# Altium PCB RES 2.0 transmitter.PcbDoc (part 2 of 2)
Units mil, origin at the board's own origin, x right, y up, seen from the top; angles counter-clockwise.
Board outline 3335 x 2413 mil, 2 copper layers (Top Layer, Bottom Layer); 59 components, 51 nets, 223 pads, 116 vias.
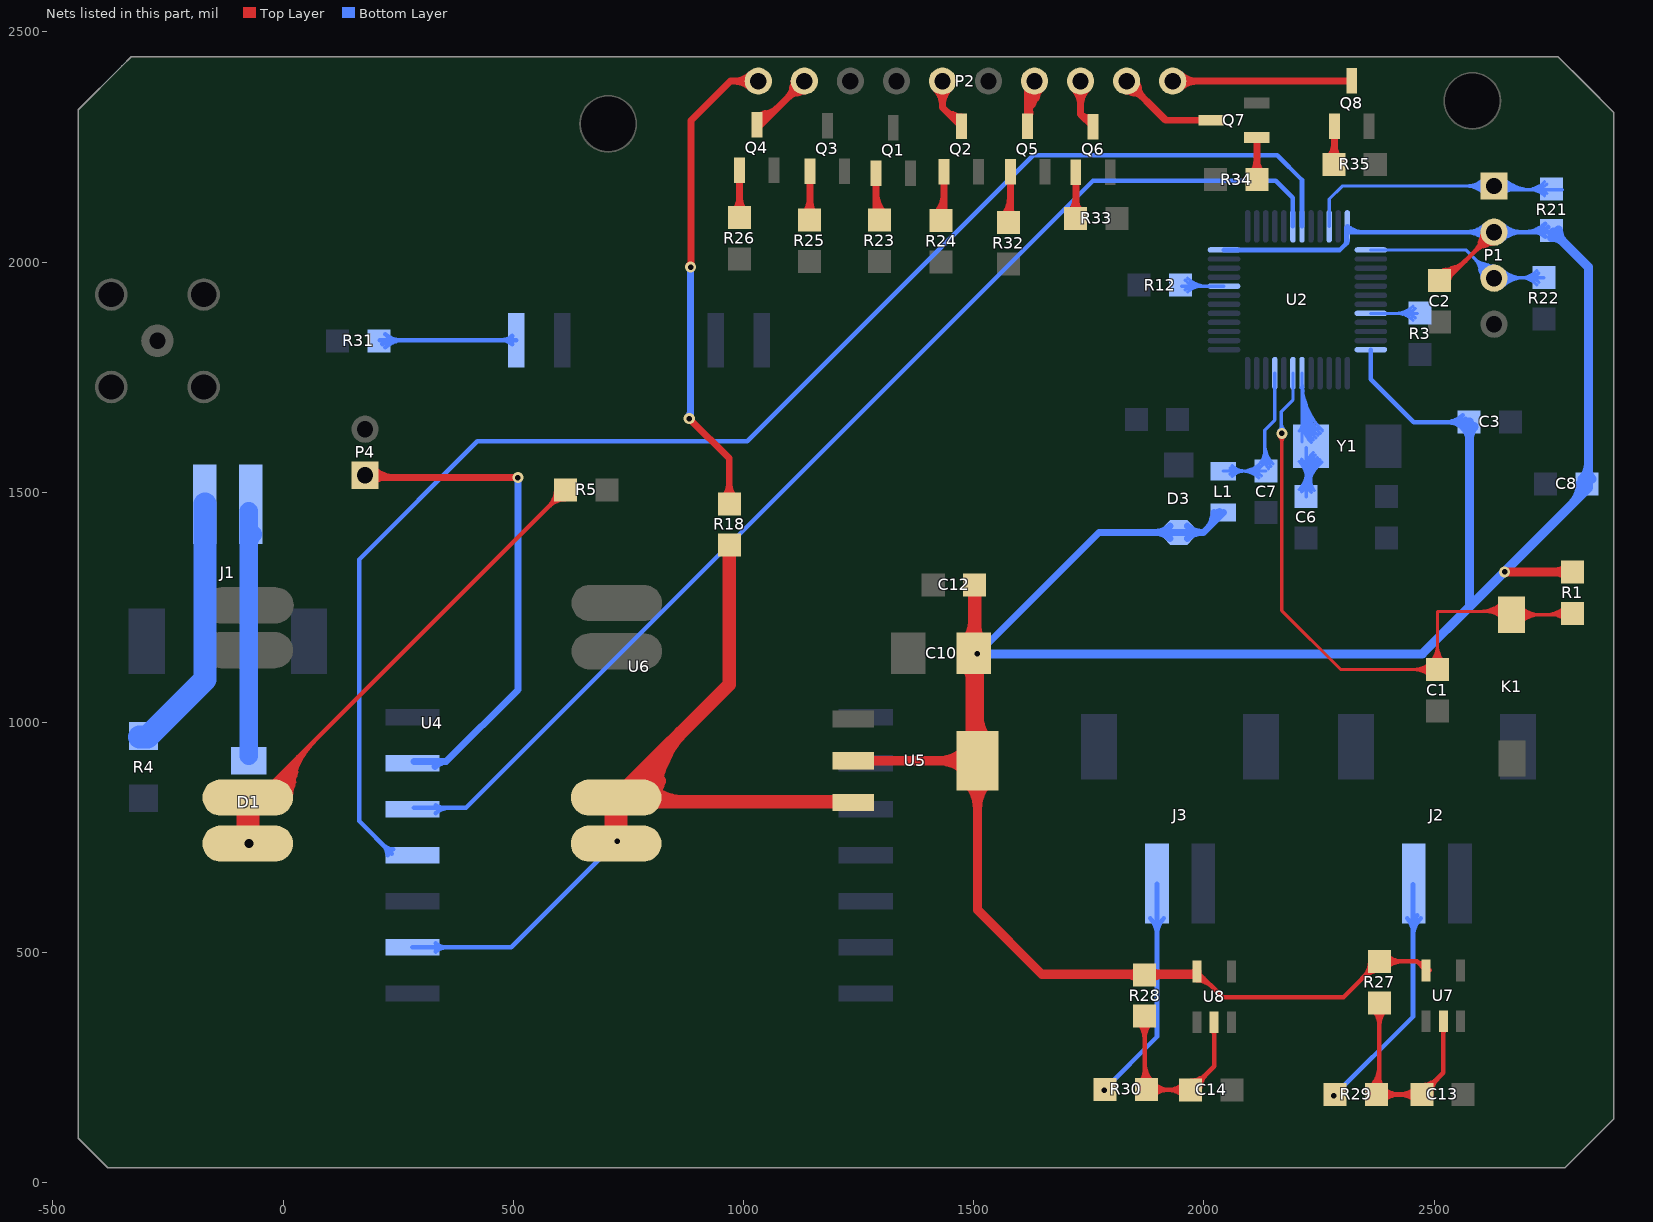
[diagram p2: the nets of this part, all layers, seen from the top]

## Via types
v1: diameter 24, hole 12, Top Layer to Bottom Layer, 115 vias
v2: diameter 40, hole 20, Top Layer to Bottom Layer, 1 vias

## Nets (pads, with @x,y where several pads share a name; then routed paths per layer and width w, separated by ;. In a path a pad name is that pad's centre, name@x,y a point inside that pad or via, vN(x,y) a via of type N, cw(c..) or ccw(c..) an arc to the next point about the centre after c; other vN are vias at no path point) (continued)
NetC6_2: C6.2 U2.6 Y1.1 | length 2958.8
  Bottom Layer w7: U2.6@2211.37,1727.12 cw(c2204.53,1718.24) 2215.65,1719.68 ; Y1.1@2212.84,1609.42 U2.6@2212.84,1758.55 ; 2213.02,1722.3 cw(c2220.09,1722.88) U2.6@2214.68,1727.47 ; 2217.94,1647.87 ccw(c2225.88,1652.46) Y1.1@2227.18,1643.38 ; 2220.47,1657.02 ccw(c2245.99,1671.75) Y1.1@2239.8,1642.94 ; C6.2@2222,1491 Y1.1@2222,1596.74 ; 2231.39,1648.9 ccw(c2242.91,1656.26) Y1.1@2239.97,1642.91 ; C6.2@2212,1510.03 ccw(c2199.11,1534.57) 2226.36,1529.54 ; C6.2@2212,1510.03 ccw(c2199.11,1534.57) 2226.36,1529.54 ; C6.2@2212,1510.03 ccw(c2199.11,1534.57) 2226.36,1529.54 ; C6.2@2212.42,1510.25 ccw(c2194.93,1545.37) 2233.07,1536.13 ; C6.2@2212.42,1510.25 ccw(c2194.93,1545.37) 2233.07,1536.13 ; C6.2@2212.42,1510.25 ccw(c2194.93,1545.37) 2233.07,1536.13 ; C6.2@2215.54,1503.98 ccw(c2203.7,1527.77) 2229.52,1521.51 ; C6.2@2215.54,1503.98 ccw(c2203.7,1527.77) 2229.52,1521.51 ; C6.2@2215.54,1503.98 ccw(c2203.7,1527.77) 2229.52,1521.51 ; 2222,1526.01 cw(c2186.99,1526.01) 2211.75,1501.25 ccw(c2186.99,1526.01) 2222,1526.01 ; 2222,1526.01 ccw(c2257.01,1526.01) 2232.25,1501.25 cw(c2257.01,1526.01) 2222,1526.01 ; 2222,1542.91 cw(c2170.09,1542.91) 2206.8,1506.2 ccw(c2170.09,1542.91) 2222,1542.91 ; 2222,1542.91 ccw(c2273.91,1542.91) 2237.2,1506.2 cw(c2273.91,1542.91) 2222,1542.91 ; 2224.33,1518.53 ccw(c2240.14,1515.62) C6.2@2230.6,1502.67 ; 2224.33,1518.53 ccw(c2240.14,1515.62) C6.2@2230.6,1502.67 ; 2224.33,1518.53 ccw(c2240.14,1515.62) C6.2@2230.6,1502.67 ; 2226.36,1529.54 ccw(c2247.52,1525.63) C6.2@2234.76,1508.31 ; 2226.36,1529.54 ccw(c2247.52,1525.63) C6.2@2234.76,1508.31 ; 2226.36,1529.54 ccw(c2247.52,1525.63) C6.2@2234.76,1508.31 ; 2229.48,1521.34 ccw(c2255.38,1515.06) C6.2@2233.76,1499.48 ; 2229.48,1521.34 ccw(c2255.38,1515.06) C6.2@2233.76,1499.48 ; 2229.48,1521.34 ccw(c2255.38,1515.06) C6.2@2233.76,1499.48 ; 2233.07,1536.13 ccw(c2271.63,1526.78) C6.2@2239.44,1503.57 ; 2233.07,1536.13 ccw(c2271.63,1526.78) C6.2@2239.44,1503.57 ; 2233.07,1536.13 ccw(c2271.63,1526.78) C6.2@2239.44,1503.57 ; Y1.1@2206.9,1566.76 cw(c2170.43,1530.3) 2222,1530.3 ccw(c2170.43,1530.3) Y1.1@2206.9,1566.76 ; Y1.1@2206.9,1633.24 ccw(c2192.54,1647.59) 2212.84,1647.59 cw(c2192.54,1647.59) Y1.1@2206.9,1633.24 ; Y1.1@2211.85,1571.71 cw(c2187.33,1547.2) 2222,1547.2 ccw(c2187.33,1547.2) Y1.1@2211.85,1571.71 ; 2212.84,1656.85 ccw(c2281.24,1656.85) 2232.88,1608.49 cw(c2281.24,1656.85) 2212.84,1656.85 ; 2212.84,1673.75 ccw(c2298.14,1673.75) 2237.82,1613.44 cw(c2298.14,1673.75) 2212.84,1673.75 ; 2212.84,1690.65 ccw(c2315.04,1690.65) 2242.77,1618.39 cw(c2315.04,1690.65) 2212.84,1690.65 ; 2212.84,1707.55 ccw(c2331.94,1707.55) 2247.72,1623.34 cw(c2331.94,1707.55) 2212.84,1707.55 ; U2.6@2212.84,1724.45 ccw(c2348.84,1724.45) 2252.67,1628.29 cw(c2348.84,1724.45) U2.6@2212.84,1724.45 ; U2.6@2212.84,1741.35 ccw(c2365.74,1741.35) 2257.62,1633.24 cw(c2365.74,1741.35) U2.6@2212.84,1741.35 ; C6.2@2222,1490.48 cw(c2321.17,1490.48) 2255.88,1565.13 ccw(c2321.17,1490.48) C6.2@2222,1490.48 ; C6.2@2222,1505.91 cw(c2307.68,1505.91) 2251.27,1570.4 ccw(c2307.68,1505.91) C6.2@2222,1505.91 ; 2222,1521.33 cw(c2294.19,1521.33) 2246.66,1575.67 ccw(c2294.19,1521.33) 2222,1521.33 ; 2222,1536.76 cw(c2280.7,1536.76) 2242.05,1580.93 ccw(c2280.7,1536.76) 2222,1536.76 ; 2222,1552.18 cw(c2267.2,1552.18) 2237.44,1586.2 ccw(c2267.2,1552.18) 2222,1552.18
NetC7_2: C7.2 L1.2 U2.9 | length 1085.4
  Bottom Layer w7: L1.2@2042,1546 C7.2@2135,1546 ; C7.2@2132,1563 2132,1635 2153.79,1656.79 U2.9@2153.79,1758.55 ; 2072.43,1546 cw(c2072.43,1568.93) 2056.22,1552.72 ccw(c2072.43,1568.93) 2072.43,1546 ; 2072.43,1546 ccw(c2072.43,1523.07) 2056.22,1539.28 cw(c2072.43,1523.07) 2072.43,1546 ; 2083.09,1546 cw(c2083.09,1494.09) 2119.8,1530.8 ccw(c2083.09,1494.09) 2083.09,1546 ; 2083.09,1546 ccw(c2083.09,1597.91) C7.2@2119.8,1561.2 ; 2083.09,1546 ccw(c2083.09,1597.91) C7.2@2119.8,1561.2 ; 2089.33,1546 cw(c2089.33,1585.83) 2061.17,1557.67 ccw(c2089.33,1585.83) 2089.33,1546 ; 2089.33,1546 ccw(c2089.33,1506.17) 2061.17,1534.33 cw(c2089.33,1506.17) 2089.33,1546 ; 2099.99,1546 cw(c2099.99,1510.99) 2124.75,1535.75 ccw(c2099.99,1510.99) 2099.99,1546 ; 2099.99,1546 ccw(c2099.99,1581.01) C7.2@2124.75,1556.25 ; 2099.99,1546 ccw(c2099.99,1581.01) C7.2@2124.75,1556.25 ; C7.2@2119.8,1561.2 ccw(c2090.34,1590.66) 2132,1590.66 cw(c2090.34,1590.66) C7.2@2119.8,1561.2 ; C7.2@2124.75,1556.25 ccw(c2107.24,1573.76) 2132,1573.76 cw(c2107.24,1573.76) C7.2@2124.75,1556.25 ; 2132,1571.35 ccw(c2160.35,1571.35) 2140.3,1551.3 cw(c2160.35,1571.35) 2132,1571.35 ; 2132,1588.25 ccw(c2177.25,1588.25) 2145.25,1556.25 cw(c2177.25,1588.25) 2132,1588.25 ; 2132,1605.15 ccw(c2194.15,1605.15) 2150.2,1561.2 cw(c2194.15,1605.15) 2132,1605.15
NetC13_2: C13.2 R27.2 R29.1 U7.2 | length 1400
  Top Layer w10: R29.1@2381,198 R27.2@2381,391 ; R29.1@2387,192 C13.2@2473,192 ; 2498.2,218.75 ccw(c2507.24,184.99) C13.2@2473,192 ; 2499.75,217.2 cw(c2465.99,226.24) C13.2@2473,192 ; U7.2@2520,350.89 2520,239 C13.2@2473,192 ; 2381,342.72 cw(c2429.28,342.72) 2395.14,376.86 ccw(c2429.28,342.72) 2381,342.72 ; 2381,342.72 ccw(c2332.72,342.72) 2366.86,376.86 cw(c2332.72,342.72) 2381,342.72 ; R29.1@2389.14,206.14 ccw(c2423.28,240.28) 2423.28,192 ; R29.1@2389.14,206.14 cw(c2408.8,225.8) 2381,225.8 ccw(c2408.8,225.8) R29.1@2389.14,206.14 ; R29.1@2389.14,206.14 ccw(c2423.28,240.28) 2423.28,192 ; 2423.28,192 ccw(c2423.28,143.72) 2389.14,177.86 cw(c2423.28,143.72) 2423.28,192 ; 2424.72,192 cw(c2424.72,143.72) 2458.86,177.86 ccw(c2424.72,143.72) 2424.72,192 ; 2424.72,192 ccw(c2424.72,240.28) 2458.86,206.14 cw(c2424.72,240.28) 2424.72,192 ; 2507.14,226.14 cw(c2473,260.28) 2473,212 ccw(c2473,260.28) 2507.14,226.14 ; 2507.14,226.14 ccw(c2541.28,192) 2493,192 cw(c2541.28,192) 2507.14,226.14 ; 2520,325.41 cw(c2531.69,325.41) 2523.43,333.68 ccw(c2531.69,325.41) 2520,325.41 ; 2520,325.41 ccw(c2508.31,325.41) 2516.58,333.68 cw(c2508.31,325.41) 2520,325.41 ; R29.1@2360.86,206.14 ccw(c2312.23,254.77) 2381,254.77 cw(c2312.23,254.77) R29.1@2360.86,206.14 ; R29.1@2367.93,199.07 ccw(c2336.37,230.63) 2381,230.63 cw(c2336.37,230.63) R29.1@2367.93,199.07
NetC14_2: C14.2 R28.2 R30.1 U8.2 | length 1393.2
  Top Layer w10: R30.1@1871,207 R28.2@1871,362 ; R30.1@1876,202 C14.2@1971,202 ; 1996.2,228.75 ccw(c2005.24,194.99) C14.2@1971,202 ; 1997.75,227.2 cw(c1963.99,236.24) C14.2@1971,202 ; U8.2@2022,348.89 2022,253 C14.2@1971,202 ; 1871,313.72 cw(c1919.28,313.72) 1885.14,347.86 ccw(c1919.28,313.72) 1871,313.72 ; 1871,313.72 ccw(c1822.72,313.72) 1856.86,347.86 cw(c1822.72,313.72) 1871,313.72 ; R30.1@1882.07,210.07 ccw(c1901.56,229.56) 1901.56,202 cw(c1901.56,229.56) R30.1@1882.07,210.07 ; R30.1@1882.07,210.07 cw(c1908.8,236.8) 1871,236.8 ccw(c1908.8,236.8) R30.1@1882.07,210.07 ; R30.1@1889.14,217.14 ccw(c1925.7,253.7) 1925.7,202 cw(c1925.7,253.7) R30.1@1889.14,217.14 ; R30.1@1889.14,217.14 cw(c1932.94,260.94) 1871,260.94 ccw(c1932.94,260.94) R30.1@1889.14,217.14 ; 1922.72,202 cw(c1922.72,153.72) 1956.86,187.86 ccw(c1922.72,153.72) 1922.72,202 ; 1922.72,202 ccw(c1922.72,250.28) 1956.86,216.14 cw(c1922.72,250.28) 1922.72,202 ; 2005.14,236.14 cw(c1971,270.28) 1971,222 ccw(c1971,270.28) 2005.14,236.14 ; 2005.14,236.14 ccw(c2039.28,202) 1991,202 cw(c2039.28,202) 2005.14,236.14 ; 2022,323.41 cw(c2033.69,323.41) 2025.43,331.68 ccw(c2033.69,323.41) 2022,323.41 ; 2022,323.41 ccw(c2010.31,323.41) 2018.58,331.68 cw(c2010.31,323.41) 2022,323.41 ; R30.1@1860.86,217.14 ccw(c1836.37,241.63) 1871,241.63 cw(c1836.37,241.63) R30.1@1860.86,217.14 ; R30.1@1889.14,188.86 cw(c1920.87,157.13) 1920.87,202 ccw(c1920.87,157.13) R30.1@1889.14,188.86
NetD1_1: D1.1 J1.2 | length 579
  Bottom Layer w40: D1.1@-75,928.03 J1.2@-75,1459 ; J1.2@-75,1387.41 cw(c-44.43,1387.41) -66.05,1409.02 ccw(c-44.43,1387.41) J1.2@-75,1387.41
NetJ1_1: J1.1 R4.1 | length 574.8
  Bottom Layer w50: R4.1@-312,968 -295,968 -170,1093 J1.1@-170,1474
NetJ2_2: J2.2 R29.2 | length 790.4
  Bottom Layer w10: v1(2282,189) 2454,361 J2.2@2454,648 ; 2293.95,200.95 cw(c2282,212.9) 2282,196 ccw(c2282,212.9) 2293.95,200.95 ; 2293.95,200.95 ccw(c2305.9,189) 2289,189 cw(c2305.9,189) 2293.95,200.95 ; J2.2@2441.44,574.42 cw(c2411.12,544.1) 2454,544.1 ccw(c2411.12,544.1) J2.2@2441.44,574.42 ; 2454,534.44 cw(c2510.54,534.44) 2470.56,574.42 ccw(c2510.54,534.44) 2454,534.44 ; 2454,558.58 cw(c2486.4,558.58) 2463.49,581.49 ccw(c2486.4,558.58) 2454,558.58
NetJ3_2: J3.2 R30.2 | length 704.9
  Bottom Layer w10: v1@1783,202 1898,317 J3.2@1898,650 ; 1898,539.27 cw(c1947.71,539.27) 1912.56,574.42 ccw(c1947.71,539.27) 1898,539.27 ; 1898,539.27 ccw(c1848.29,539.27) 1883.44,574.42 cw(c1848.29,539.27) 1898,539.27 ; v1@1783,208 ccw(c1783,222.49) 1793.24,212.24 cw(c1783,222.49) v1@1783,208 ; v1@1790,201 cw(c1809.31,201) 1795.66,214.66 ccw(c1809.31,201) v1@1790,201
  other v1: 1783,201
NetP2_1: P2.1 R18.1 | length 1401
  Top Layer w15: v1(882,1660) 969,1573 R18.1@969,1475 ; v1@886,1990 886,2307 972,2393 P2.1@1032,2393 ; 969,1517.25 cw(c926.75,1517.25) 956.63,1487.37 ccw(c926.75,1517.25) 969,1517.25 ; 969,1517.25 ccw(c1011.25,1517.25) 981.37,1487.37 cw(c1011.25,1517.25) 969,1517.25 ; 978.82,2393 cw(c978.82,2339.82) 1016.42,2377.42 ccw(c978.82,2339.82) 978.82,2393 ; 978.82,2393 ccw(c978.82,2446.18) 1016.42,2408.58 cw(c978.82,2446.18) 978.82,2393 ; v1@881.82,1992.18 ccw(c871.72,2002.28) 886,2002.28 cw(c871.72,2002.28) v1@881.82,1992.18
  Bottom Layer w15: v1@885,1663 v1(885,1989) ; v1@878.82,1663.18 ccw(c863.89,1678.11) 885,1678.11 cw(c863.89,1678.11) v1@878.82,1663.18
NetP4_1: P4.1 U6.2 | length 1307.5
  Top Layer w15: P4.1@178,1537 183,1532 v1(510,1532) ; P4.1@193.58,1521.42 cw(c219.11,1495.89) 219.11,1532 ccw(c219.11,1495.89) P4.1@193.58,1521.42 ; P4.1@193.58,1552.58 ccw(c243.25,1602.25) 243.25,1532 cw(c243.25,1602.25) P4.1@193.58,1552.58
  Bottom Layer w15: U6.2@284.18,915.19 354.19,915.19 ; v1(510,1532) 510,1071 354.19,915.19 ; 354.19,915.19 ccw(c354.19,881.58) 329.67,904.56 cw(c354.19,881.58) 354.19,915.19
NetQ1_1: Q1.1 R23.1 | length 276.5
  Top Layer w15: R23.1@1287.6,2098.4 Q1.1@1287.6,2193 ; R23.1@1282.63,2103.37 ccw(c1270.62,2115.38) 1287.6,2115.38 cw(c1270.62,2115.38) R23.1@1282.63,2103.37 ; R23.1@1287.6,2114.9 ccw(c1318.9,2114.9) 1296.77,2092.77 cw(c1318.9,2114.9) R23.1@1287.6,2114.9 ; 1287.6,2151.12 ccw(c1355.12,2151.12) 1307.37,2103.37 cw(c1355.12,2151.12) 1287.6,2151.12
NetQ2_1: Q2.1 R24.1 | length 232.1
  Top Layer w15: R24.1@1435.6,2096.6 Q2.1@1435.6,2196 ; R24.1@1416.63,2102.37 ccw(c1370.82,2148.18) 1435.6,2148.18 cw(c1370.82,2148.18) R24.1@1416.63,2102.37 ; 1435.6,2116.32 ccw(c1455.32,2116.32) 1441.37,2102.37 cw(c1455.32,2116.32) 1435.6,2116.32
NetQ3_1: Q3.1 R25.1 | length 237.1
  Top Layer w15: R25.1@1144.6,2092.6 Q3.1@1144.6,2197 ; R25.1@1130.63,2103.37 ccw(c1096.89,2137.11) 1144.6,2137.11 cw(c1096.89,2137.11) R25.1@1130.63,2103.37 ; 1144.6,2129.39 ccw(c1181.39,2129.39) 1155.37,2103.37 cw(c1181.39,2129.39) 1144.6,2129.39
NetQ4_1: Q4.1 R26.1 | length 234.1
  Top Layer w15: R26.1@991.6,2097.6 Q4.1@991.6,2199 ; R26.1@978.63,2109.37 ccw(c947.31,2140.69) 991.6,2140.69 cw(c947.31,2140.69) R26.1@978.63,2109.37 ; 991.6,2137.8 ccw(c1031.8,2137.8) 1003.37,2109.37 cw(c1031.8,2137.8) 991.6,2137.8
NetQ5_1: Q5.1 R32.1 | length 238.1
  Top Layer w15: R32.1@1579.6,2090.6 Q5.1@1579.6,2196 ; R32.1@1562.63,2098.37 ccw(c1521.65,2139.35) 1579.6,2139.35 cw(c1521.65,2139.35) R32.1@1562.63,2098.37 ; 1579.6,2117.15 ccw(c1606.15,2117.15) 1587.37,2098.37 cw(c1606.15,2117.15) 1579.6,2117.15
NetQ6_1: Q6.1 R33.1 | length 233
  Top Layer w15: Q6.1@1721,2194.4 Q6.1@1721.6,2195 R33.1@1721.6,2095.6 ; R33.1@1708.63,2107.37 ccw(c1677.31,2138.69) 1721.6,2138.69 cw(c1677.31,2138.69) R33.1@1708.63,2107.37 ; 1721.6,2135.8 ccw(c1761.8,2135.8) 1733.37,2107.37 cw(c1761.8,2135.8) 1721.6,2135.8
NetQ7_1: Q7.1 R34.1 | length 224.3
  Top Layer w15: R34.1@2115,2179 Q7.1@2115,2270.6 ; 2115,2221.25 cw(c2072.75,2221.25) 2102.63,2191.37 ccw(c2072.75,2221.25) 2115,2221.25 ; 2115,2221.25 ccw(c2157.25,2221.25) 2127.37,2191.37 cw(c2157.25,2221.25) 2115,2221.25
NetQ8_1: Q8.1 R35.1 | length 214.1
  Top Layer w15: R35.1@2283.6,2213.6 Q8.1@2283.6,2295 ; R35.1@2269.63,2224.37 ccw(c2235.89,2258.11) 2283.6,2258.11 cw(c2235.89,2258.11) R35.1@2269.63,2224.37 ; 2283.6,2250.39 ccw(c2320.39,2250.39) 2294.37,2224.37 cw(c2320.39,2250.39) 2283.6,2250.39
NetR3_1: R3.1 U2.44 | length 374.1
  Bottom Layer w7: U2.44@2362.45,1888.47 R3.1@2463.53,1888.47 ; 2415.82,1888.47 ccw(c2415.82,1942.18) 2453.8,1904.2 cw(c2415.82,1942.18) 2415.82,1888.47 ; 2418.37,1888.47 cw(c2418.37,1838.37) 2453.8,1873.8 ccw(c2418.37,1838.37) 2418.37,1888.47 ; 2432.72,1888.47 ccw(c2432.72,1925.28) 2458.75,1899.25 cw(c2432.72,1925.28) 2432.72,1888.47 ; 2435.27,1888.47 cw(c2435.27,1855.27) 2458.75,1878.75 ccw(c2435.27,1855.27) 2435.27,1888.47
NetR12_2: R12.2 U2.20 | length 365.1
  Bottom Layer w7: R12.2@1951.53,1947.53 U2.20@2043.55,1947.53 ; R12.2@1959.25,1939.75 cw(c1978.04,1920.96) 1978.04,1947.53 ccw(c1978.04,1920.96) R12.2@1959.25,1939.75 ; R12.2@1959.25,1960.25 ccw(c1989.97,1990.97) 1989.97,1947.53 cw(c1989.97,1990.97) R12.2@1959.25,1960.25 ; R12.2@1964.2,1934.8 cw(c1994.94,1904.06) 1994.94,1947.53 ccw(c1994.94,1904.06) R12.2@1964.2,1934.8 ; R12.2@1964.2,1965.2 ccw(c2006.87,2007.87) 2006.87,1947.53 cw(c2006.87,2007.87) R12.2@1964.2,1965.2
NetR31_2: R31.2 U6.18 | length 590.8
  Bottom Layer w10: R31.2@209.45,1830.45 U6.18@506.46,1830.45 ; 475.76,1830.45 cw(c475.76,1799.75) 497.47,1821.46 ccw(c475.76,1799.75) 475.76,1830.45 ; 475.76,1830.45 ccw(c475.76,1861.15) 497.47,1839.44 cw(c475.76,1861.15) 475.76,1830.45 ; R31.2@215.07,1821.93 cw(c235.64,1801.36) 235.64,1830.45 ccw(c235.64,1801.36) R31.2@215.07,1821.93 ; R31.2@222.14,1814.86 cw(c259.78,1777.22) 259.78,1830.45 ccw(c259.78,1777.22) R31.2@222.14,1814.86 ; R31.2@222.14,1843.14 ccw(c252.79,1873.79) 252.79,1830.45 cw(c252.79,1873.79) R31.2@222.14,1843.14
POWER1: P2.7 Q5.3 | length 497.1
  Top Layer w15: Q5.3@1614.85,2314.45 ccw(c1606.51,2328.9) 1622.62,2324.58 ; Q5.3@1617,2294.97 1617,2378 P2.7@1632,2393 ; P2.7@1618.42,2375.66 cw(c1611.34,2366.61) 1621.29,2360.87 cw(c1640.09,2350.01) P2.7@1636.08,2371.35 ; P2.7@1619.3,2375.01 cw(c1604.52,2354.08) 1626.7,2341.27 ; P2.7@1627.95,2387.26 cw(c1614.04,2367.56) 1634.92,2355.51 ; Q5.3@1617,2303.62 cw(c1721.38,2303.62) 1647.58,2377.42 ccw(c1721.38,2303.62) Q5.3@1617,2303.62 ; 1617,2339.83 cw(c1685.17,2339.83) 1636.97,2388.03 ccw(c1685.17,2339.83) 1617,2339.83
POWER2: P2.8 Q6.3 | length 352.9
  Top Layer w15: P2.8@1732,2393 1732,2320.98 ; 1738.58,2314.08 cw(c1738.35,2289.46) Q6.3@1755.93,2306.7 ; Q6.3@1759,2293.97 1732,2320.98 ; 1732,2320.98 ccw(c1751.17,2340.14) 1757.93,2313.9 cw(c1751.17,2340.14) 1732,2320.98 ; 1732,2339.82 cw(c1785.18,2339.82) 1747.58,2377.42 ccw(c1785.18,2339.82) 1732,2339.82 ; 1732,2339.82 ccw(c1678.82,2339.82) 1716.42,2377.42 cw(c1678.82,2339.82) 1732,2339.82
POWER3: P2.9 Q7.3 | length 457.3
  Top Layer w15: P2.9@1824.19,2391.4 ccw(c1855.58,2397.83) 1847.29,2366.88 ; P2.9@1832,2393 1917,2308 Q7.3@2016.03,2308 ; P2.9@1833.6,2400.81 cw(c1827.17,2369.42) 1858.12,2377.71 ; 1869.6,2355.4 cw(c1907.21,2393) 1854.03,2393 ccw(c1907.21,2393) 1869.6,2355.4 ; 1869.6,2355.4 ccw(c1832,2317.79) 1832,2370.97 cw(c1832,2317.79) 1869.6,2355.4
POWER4: P2.10 Q8.3 | length 576.7
  Top Layer w15: P2.10@1932,2393 Q8.3@2320.03,2393 ; 1985.18,2393 cw(c1985.18,2446.18) 1947.58,2408.58 ccw(c1985.18,2446.18) 1985.18,2393 ; 1985.18,2393 ccw(c1985.18,2339.82) 1947.58,2377.42 cw(c1985.18,2339.82) 1985.18,2393 ; 2308.25,2393 ccw(c2308.25,2406.73) 2317.96,2397.02 cw(c2308.25,2406.73) 2308.25,2393
RED: P2.2 Q4.3 | length 547.4
  Top Layer w15: Q4.3@1032.74,2311.57 cw(c1054.06,2299.25) 1047.69,2323.04 ; Q4.3@1036.97,2297.97 P2.2@1132,2393 ; 1105.88,2377.71 cw(c1136.83,2369.42) P2.2@1130.4,2400.81 ; 1116.71,2366.88 ccw(c1108.42,2397.83) P2.2@1139.81,2391.4 ; 1094.4,2355.4 cw(c1132,2317.79) 1132,2370.97 ccw(c1132,2317.79) 1094.4,2355.4 ; 1094.4,2355.4 ccw(c1056.79,2393) 1109.97,2393 cw(c1056.79,2393) 1094.4,2355.4 ; Q4.3@1029,2303.03 ccw(c1029,2334.48) 1051.24,2312.24 cw(c1029,2334.48) Q4.3@1029,2303.03 ; Q4.3@1029,2318.03 ccw(c1029,2385.69) 1076.85,2337.85 cw(c1029,2385.69) Q4.3@1029,2318.03
RESET: C1.2 K1.2 R1.1 U2.7 | length 3062.5
  Top Layer w7: v1(2169,1628) 2169,1243 2297,1115 C1.2@2507,1115 2507,1241 K1.2@2661,1241 ; K1.2@2668,1234 R1.1@2797,1234 ; 2169,1607.48 cw(c2189.52,1607.48) 2175.01,1621.99 ccw(c2189.52,1607.48) 2169,1607.48 ; 2169,1607.48 ccw(c2148.48,1607.48) 2162.99,1621.99 cw(c2148.48,1607.48) 2169,1607.48 ; 2455.09,1115 cw(c2455.09,1063.09) 2491.8,1099.8 ccw(c2455.09,1063.09) 2455.09,1115 ; 2455.09,1115 ccw(c2455.09,1166.91) C1.2@2491.8,1130.2 ; 2455.09,1115 ccw(c2455.09,1166.91) C1.2@2491.8,1130.2 ; 2471.99,1115 cw(c2471.99,1079.99) 2496.75,1104.75 ccw(c2471.99,1079.99) 2471.99,1115 ; 2471.99,1115 ccw(c2471.99,1150.01) C1.2@2496.75,1125.25 ; 2471.99,1115 ccw(c2471.99,1150.01) C1.2@2496.75,1125.25 ; C1.2@2491.8,1130.2 ccw(c2455.09,1166.91) 2507,1166.91 ; C1.2@2491.8,1130.2 ccw(c2455.09,1166.91) 2507,1166.91 ; C1.2@2496.75,1125.25 ccw(c2471.99,1150.01) 2507,1150.01 ; C1.2@2496.75,1125.25 ccw(c2471.99,1150.01) 2507,1150.01 ; 2507,1150.01 ccw(c2542.01,1150.01) 2517.25,1125.25 cw(c2542.01,1150.01) 2507,1150.01 ; 2507,1166.91 ccw(c2558.91,1166.91) 2522.2,1130.2 cw(c2558.91,1166.91) 2507,1166.91 ; 2713.94,1234 cw(c2713.94,1279.94) 2681.45,1247.45 ccw(c2713.94,1279.94) 2713.94,1234 ; 2713.94,1234 ccw(c2713.94,1188.06) 2681.45,1220.55 cw(c2713.94,1188.06) 2713.94,1234 ; 2730.84,1234 cw(c2730.84,1296.84) 2686.4,1252.4 ccw(c2730.84,1296.84) 2730.84,1234 ; 2730.84,1234 ccw(c2730.84,1171.16) 2686.4,1215.6 cw(c2730.84,1171.16) 2730.84,1234 ; 2598.3,1241 ccw(c2598.3,1313.54) 2649.6,1262.25 cw(c2598.3,1313.54) 2598.3,1241 ; 2612.03,1241 cw(c2612.03,1187.87) 2649.6,1225.44 ccw(c2612.03,1187.87) 2612.03,1241 ; 2615.2,1241 ccw(c2615.2,1296.64) 2654.55,1257.3 cw(c2615.2,1296.64) 2615.2,1241 ; 2628.93,1241 cw(c2628.93,1204.77) 2654.55,1230.39 ccw(c2628.93,1204.77) 2628.93,1241 ; 2632.1,1241 ccw(c2632.1,1279.74) 2659.5,1252.35 cw(c2632.1,1279.74) 2632.1,1241 ; 2740.85,1234 ccw(c2740.85,1296.15) 2784.8,1252.2 cw(c2740.85,1296.15) 2740.85,1234 ; 2755.34,1234 cw(c2755.34,1192.34) 2784.8,1221.8 ccw(c2755.34,1192.34) 2755.34,1234 ; 2757.75,1234 ccw(c2757.75,1279.25) 2789.75,1247.25 cw(c2757.75,1279.25) 2757.75,1234 ; 2772.24,1234 cw(c2772.24,1209.24) 2789.75,1226.75 ccw(c2772.24,1209.24) 2772.24,1234 ; 2774.65,1234 ccw(c2774.65,1262.35) 2794.7,1242.3 cw(c2774.65,1262.35) 2774.65,1234
  Bottom Layer w7: v1@2164,1630 2167.79,1633.79 2167.79,1674.79 2193.16,1700.16 U2.7@2193.16,1758.55 ; v1@2162.99,1634.01 ccw(c2151.41,1645.59) 2167.79,1645.59 cw(c2151.41,1645.59) v1@2162.99,1634.01 ; 2167.79,1651.45 ccw(c2192.45,1651.45) 2175.01,1634.01 cw(c2192.45,1651.45) 2167.79,1651.45
SWCLK: P1.3 R22.1 U2.37 | length 1589.2
  Bottom Layer w7: U2.37@2362.45,2026.27 2568.73,2026.27 P1.3@2630,1965 ; 2596.01,1994.71 ccw(c2638.41,2006.07) P1.3@2629.6,1963.07 ; 2598.94,1983.77 ccw(c2635.87,1993.66) P1.3@2628.2,1956.21 ; 2600.29,1998.99 cw(c2588.93,1956.59) P1.3@2631.93,1965.4 ; 2611.23,1996.06 cw(c2601.34,1959.13) P1.3@2638.79,1966.8 ; P1.3@2631,1966 R22.1@2738,1966 ; 2585.57,2009.43 cw(c2541.14,1965) 2603.97,1965 ccw(c2541.14,1965) 2585.57,2009.43 ; 2585.57,2009.43 ccw(c2630,2053.86) 2630,1991.03 cw(c2630,2053.86) 2585.57,2009.43 ; 2597.52,1997.48 cw(c2565.04,1965) 2610.97,1965 ccw(c2565.04,1965) 2597.52,1997.48 ; 2597.52,1997.48 ccw(c2630,2029.96) 2630,1984.03 cw(c2630,2029.96) 2597.52,1997.48 ; 2686.09,1966 cw(c2686.09,1914.09) 2722.8,1950.8 ccw(c2686.09,1914.09) 2686.09,1966 ; 2686.09,1966 ccw(c2686.09,2017.91) 2722.8,1981.2 cw(c2686.09,2017.91) 2686.09,1966 ; 2702.99,1966 cw(c2702.99,1930.99) 2727.75,1955.75 ccw(c2702.99,1930.99) 2702.99,1966 ; 2702.99,1966 ccw(c2702.99,2001.01) 2727.75,1976.25 cw(c2702.99,2001.01) 2702.99,1966 ; P1.3@2638.5,1956.5 cw(c2661.45,1933.55) 2661.45,1966 ccw(c2661.45,1933.55) P1.3@2638.5,1956.5 ; P1.3@2643.45,1951.55 cw(c2678.35,1916.65) 2678.35,1966 ccw(c2678.35,1916.65) P1.3@2643.45,1951.55 ; P1.3@2643.45,1978.45 ccw(c2673.52,2008.52) 2673.52,1966 cw(c2673.52,2008.52) P1.3@2643.45,1978.45 ; P1.3@2648.4,1946.6 cw(c2695.25,1899.75) 2695.25,1966 ccw(c2695.25,1899.75) P1.3@2648.4,1946.6 ; P1.3@2648.4,1983.4 ccw(c2690.42,2025.42) 2690.42,1966 cw(c2690.42,2025.42) P1.3@2648.4,1983.4
SWDIO: P1.1 R21.1 U2.34 | length 1646.9
  Bottom Layer w7: U2.34@2271.9,2077.45 2271.9,2136.9 2300,2165 P1.1@2630,2165 ; P1.1@2638,2157 R21.1@2778,2157 ; 2567.16,2165 cw(c2567.16,2102.16) 2611.6,2146.6 ccw(c2567.16,2102.16) 2567.16,2165 ; 2567.16,2165 ccw(c2567.16,2227.84) 2611.6,2183.4 cw(c2567.16,2227.84) 2567.16,2165 ; 2584.06,2165 cw(c2584.06,2119.06) 2616.55,2151.55 ccw(c2584.06,2119.06) 2584.06,2165 ; 2584.06,2165 ccw(c2584.06,2210.94) 2616.55,2178.45 cw(c2584.06,2210.94) 2584.06,2165 ; P1.1@2633.55,2168.55 ccw(c2661.45,2196.45) 2661.45,2157 cw(c2661.45,2196.45) P1.1@2633.55,2168.55 ; P1.1@2638.5,2173.5 ccw(c2678.35,2213.35) 2678.35,2157 cw(c2678.35,2213.35) P1.1@2638.5,2173.5 ; P1.1@2643.45,2178.45 ccw(c2695.25,2230.25) 2695.25,2157 cw(c2695.25,2230.25) P1.1@2643.45,2178.45 ; P1.1@2648.4,2146.6 cw(c2673.52,2121.48) 2673.52,2157 ccw(c2673.52,2121.48) P1.1@2648.4,2146.6 ; P1.1@2648.4,2183.4 ccw(c2712.15,2247.15) 2712.15,2157 cw(c2712.15,2247.15) P1.1@2648.4,2183.4 ; 2698.27,2157 ccw(c2698.27,2215.73) 2739.8,2174.2 cw(c2698.27,2215.73) 2698.27,2157 ; 2707.92,2157 cw(c2707.92,2111.92) 2739.8,2143.8 ccw(c2707.92,2111.92) 2707.92,2157 ; 2715.17,2157 ccw(c2715.17,2198.83) 2744.75,2169.25 cw(c2715.17,2198.83) 2715.17,2157 ; 2724.82,2157 cw(c2724.82,2128.82) 2744.75,2148.75 ccw(c2724.82,2128.82) 2724.82,2157
UART1_RX: U2.31 U6.4 | length 3299.1
  Bottom Layer w10: U6.4@235.81,715.19 165,786 165,1354 422,1611 1008,1611 1629,2232 2159,2232 2212.84,2178.16 U2.31@2212.84,2077.45 ; 217.68,733.32 ccw(c239.54,755.18) 239.54,724.27 cw(c239.54,755.18) 217.68,733.32 ; 217.89,733.11 cw(c196.33,711.55) 226.82,711.55 ccw(c196.33,711.55) 217.89,733.11
UART1_TX: U2.30 U6.3 | length 2647.3
  Bottom Layer w10: U6.3@284.18,815.19 397.19,815.19 1759,2177 2156,2177 2193.16,2139.84 U2.30@2193.16,2077.45 ; U6.3@331.2,802.56 cw(c361.7,772.07) 361.7,815.19 ccw(c361.7,772.07) U6.3@331.2,802.56 ; U6.3@331.2,820.54 ccw(c344.13,833.47) 344.13,815.19 cw(c344.13,833.47) U6.3@331.2,820.54
VCC: D1.2 R5.2 U4.7 U4.8 | length 2774
  Top Layer w10: U4.7@-55,837 R5.2@613,1505 ; U4.7@-25.91,859.92 ccw(c-47.96,920.97) 14.74,904.17 ; U4.7@-23.82,849.97 ccw(c-61.89,929.78) 24.08,909.1 ; U4.7@-22.51,850.52 ccw(c-40.03,899.02) 9.78,885.67 ; U4.7@-21.87,861 ccw(c-26.25,885.79) -1.93,879.28 ; U4.7@-19.51,840.94 ccw(c-50.26,905.41) 19.18,888.7 ; U4.7@-15.21,831.92 ccw(c-38.64,881.03) 14.27,868.3 ; U4.7@-14.73,832.18 ccw(c-62.42,911.44) 28.2,892.85 ; U4.7@-9.57,823.61 ccw(c-46.45,884.89) 23.62,870.52 ; -3.07,875.03 ccw(c22.44,868.19) U4.7@1.6,851.97 ; 8.58,881.19 ccw(c42.95,871.98) U4.7@12.13,854.19 ; 586.25,1479.8 cw(c620.01,1470.76) R5.2@613,1505 ; 587.8,1478.25 ccw(c578.76,1512.01) R5.2@613,1505 ; 578.86,1470.86 cw(c613,1436.72) 613,1485 ccw(c613,1436.72) 578.86,1470.86 ; 578.86,1470.86 ccw(c544.72,1505) 593,1505 cw(c544.72,1505) 578.86,1470.86 ; U4.7@-23.26,837 cw(c53.36,837) -0.82,891.18 ccw(c53.36,837) U4.7@-23.26,837 ; U4.7@-13.26,837 cw(c87.5,837) 16.25,908.25 ccw(c87.5,837) U4.7@-13.26,837 ; U4.7@-3.26,837 cw(c121.65,837) 33.32,925.32 ccw(c121.65,837) U4.7@-3.26,837 ; U4.7@6.74,837 cw(c155.79,837) 50.39,942.39 ccw(c155.79,837) U4.7@6.74,837 ; U4.7@16.74,837 cw(c189.93,837) 67.47,959.47 ccw(c189.93,837) U4.7@16.74,837
  Top Layer w50: U4.8@-76.69,737 U4.7@-76.69,837
  other v2: -74,737
VCC3V3: C2.1 C3.1 C8.2 C10.1 C12.2 D3.2 L1.1 P1.2 R1.2 R21.2 R27.1 R28.1 U2.24 U2.36 U2.48 U5.2 U7.5 U8.5 | length 11263.2
  Top Layer w10: C10.1@1499.86,1150 C10.1@1502,1150 ; U8.5@1984.6,459.12 2040.72,403 2303,403 R27.1@2381,481 ; U8.5@1988.8,447.76 ccw(c2012.75,461.59) 2005.59,434.88 ; 2354.25,455.8 cw(c2388.01,446.76) R27.1@2381,481 ; 2355.8,454.25 ccw(c2346.76,488.01) R27.1@2381,481 ; U7.5@2482.6,461.12 2462.72,481 ; C2.1@2502.77,1963.84 cw(c2534.06,1950.83) C2.1@2525.28,1983.56 ; C2.1@2512,1960 cw(c2557.72,1940.98) 2544.91,1988.82 ; C2.1@2521.79,1957.98 cw(c2546.91,1952.81) 2540.27,1977.57 ; C2.1@2522,1977.32 ccw(c2529.65,1990.58) C2.1@2533.61,1975.79 ; C2.1@2525,1960 P1.2@2630,2065 ; 2599.48,2042.65 cw(c2636.61,2032.7) P1.2@2628.9,2070.36 ; 2607.65,2034.48 ccw(c2597.7,2071.61) P1.2@2635.36,2063.9 ; 2346.86,446.86 cw(c2381,412.72) 2381,461 ccw(c2381,412.72) 2346.86,446.86 ; 2346.86,446.86 ccw(c2312.72,481) 2361,481 cw(c2312.72,481) 2346.86,446.86 ; R27.1@2381,481 2462.72,481 ; 2429.28,481 cw(c2429.28,529.28) 2395.14,495.14 ccw(c2429.28,529.28) 2429.28,481 ; 2429.28,481 ccw(c2429.28,432.72) 2395.14,466.86 cw(c2429.28,432.72) 2429.28,481 ; 2462.72,481 ccw(c2472.63,490.91) 2480.04,479.01 cw(c2472.63,490.91) 2462.72,481 ; 2588.13,2023.13 cw(c2630,1981.26) 2630,2040.47 ccw(c2630,1981.26) 2588.13,2023.13 ; 2588.13,2023.13 ccw(c2546.26,2065) 2605.47,2065 cw(c2546.26,2065) 2588.13,2023.13 ; 2605.2,2040.2 cw(c2630,2015.4) 2630,2050.47 ccw(c2630,2015.4) 2605.2,2040.2 ; 2605.2,2040.2 ccw(c2580.4,2065) 2615.47,2065 cw(c2580.4,2065) 2605.2,2040.2 ; U8.5@1984.6,440.5 cw(c1984.6,395.54) 2016.39,427.33 ccw(c1984.6,395.54) U8.5@1984.6,440.5 ; U8.5@1984.6,450.5 cw(c1984.6,429.68) 1999.32,444.4 ccw(c1984.6,429.68) U8.5@1984.6,450.5 ; 2471.63,472.09 ccw(c2479.47,479.93) 2485.33,470.52 cw(c2479.47,479.93) 2471.63,472.09 ; U7.5@2480.53,463.19 ccw(c2486.3,468.96) 2490.61,462.03 cw(c2486.3,468.96) U7.5@2480.53,463.19 ; C2.1@2512,1970 ccw(c2512,2025.53) 2551.26,1986.26 cw(c2512,2025.53) C2.1@2512,1970 ; C2.1@2512,1980 ccw(c2512,2059.67) 2568.33,2003.33 cw(c2512,2059.67) C2.1@2512,1980 ; C2.1@2532,1960 cw(c2548.9,1960) 2536.95,1971.95 ccw(c2548.9,1960) C2.1@2532,1960
  Top Layer w20: U5.2@1238,917 U5.2@1508,917 1508,593 1648,453 U8.5@1978.48,453 ; v1(2653,1327) R1.2@2800,1327 ; 1285.58,917 cw(c1285.58,938.01) 1270.73,923.15 ccw(c1285.58,938.01) 1285.58,917 ; 1285.58,917 ccw(c1285.58,895.99) 1270.73,910.85 cw(c1285.58,895.99) 1285.58,917 ; 1422.84,917 cw(c1422.84,831.84) 1483.06,892.06 ccw(c1422.84,831.84) 1422.84,917 ; 1422.84,917 ccw(c1422.84,1002.16) 1483.06,941.94 cw(c1422.84,1002.16) 1422.84,917 ; 1508,812.15 cw(c1593.16,812.15) 1532.94,872.37 ccw(c1593.16,812.15) 1508,812.15 ; 1508,812.15 ccw(c1422.84,812.15) 1483.06,872.37 cw(c1422.84,812.15) 1508,812.15 ; 2763.79,1327 cw(c2763.79,1290.79) 2789.39,1316.39 ccw(c2763.79,1290.79) 2763.79,1327 ; 2763.79,1327 ccw(c2763.79,1363.21) 2789.39,1337.61 cw(c2763.79,1363.21) 2763.79,1327 ; 1832.37,453 cw(c1832.37,413.37) 1860.39,441.39 ccw(c1832.37,413.37) 1832.37,453 ; 1837.2,453 ccw(c1837.2,485.8) 1860.39,462.61 cw(c1837.2,485.8) 1837.2,453 ; R28.1@1881.61,441.39 cw(c1909.63,413.37) 1909.63,453 ccw(c1909.63,413.37) R28.1@1881.61,441.39 ; R28.1@1881.61,462.61 ccw(c1904.8,485.8) 1904.8,453 cw(c1904.8,485.8) R28.1@1881.61,462.61 ; 1970.2,453 ccw(c1970.2,473.52) 1984.71,459.01 cw(c1970.2,473.52) 1970.2,453
  Top Layer w30: C10.1@1502,1150 C12.2@1502,1299 ; C10.1@1483.95,1173.41 ccw(c1440.38,1216.98) 1502,1216.98 cw(c1440.38,1216.98) C10.1@1483.95,1173.41 ; 1502,1206.66 ccw(c1549.02,1206.66) 1515.77,1173.41 cw(c1549.02,1206.66) 1502,1206.66
  Top Layer w40: U5.2@1502,923 C10.1@1502,1150 ; C10.1@1487.49,1130.12 cw(c1452.45,1095.09) 1502,1095.09 ccw(c1452.45,1095.09) C10.1@1487.49,1130.12 ; U5.2@1490.13,954.56 ccw(c1461.46,983.22) 1502,983.22 cw(c1461.46,983.22) U5.2@1490.13,954.56 ; 1502,1012.19 ccw(c1583.51,1012.19) 1525.87,954.56 cw(c1583.51,1012.19) 1502,1012.19
  Bottom Layer w10: U2.24@2043.55,2026.27 2295.25,2026.27 2309.49,2040.5 ; U2.36@2311.27,2077.45 2309.49,2075.67 2309.49,2040.5 ; U2.36@2314.49,2065 P1.2@2630,2065 2759,2065 R21.2@2755,2069 ; U2.48@2362.45,1809.73 2362.45,1745.55 2456,1652 C3.1@2577,1652 ; 2309.49,2040.5 ccw(c2305.34,2044.65) 2310.48,2047.48 cw(c2305.34,2044.65) 2309.49,2040.5 ; 2570.79,2065 cw(c2570.79,2005.79) 2612.66,2047.66 ccw(c2570.79,2005.79) 2570.79,2065 ; 2570.79,2065 ccw(c2570.79,2124.21) 2612.66,2082.34 cw(c2570.79,2124.21) 2570.79,2065 ; 2594.93,2065 cw(c2594.93,2029.93) 2619.73,2054.73 ccw(c2594.93,2029.93) 2594.93,2065 ; 2594.93,2065 ccw(c2594.93,2100.07) 2619.73,2075.27 cw(c2594.93,2100.07) 2594.93,2065 ; 2665.07,2065 cw(c2665.07,2100.07) 2640.27,2075.27 ccw(c2665.07,2100.07) 2665.07,2065 ; 2665.07,2065 ccw(c2665.07,2029.93) 2640.27,2054.73 cw(c2665.07,2029.93) 2665.07,2065 ; 2689.21,2065 cw(c2689.21,2124.21) 2647.34,2082.34 ccw(c2689.21,2124.21) 2689.21,2065 ; 2689.21,2065 ccw(c2689.21,2005.79) 2647.34,2047.66 cw(c2689.21,2005.79) 2689.21,2065 ; 2305.74,2036.75 ccw(c2294.57,2047.92) 2310.36,2047.92 cw(c2294.57,2047.92) 2305.74,2036.75 ; 2309.49,2041.44 cw(c2317.75,2041.44) 2311.91,2047.28 ccw(c2317.75,2041.44) 2309.49,2041.44 ; U2.36@2311.91,2078.09 ccw(c2343.51,2109.69) 2343.51,2065 cw(c2343.51,2109.69) U2.36@2311.91,2078.09 ; 2525.3,1652 ccw(c2525.3,1703.7) 2561.86,1667.14 cw(c2525.3,1703.7) 2525.3,1652 ; 2530.13,1652 cw(c2530.13,1607.13) 2561.86,1638.86 ccw(c2530.13,1607.13) 2530.13,1652 ; 2549.44,1652 ccw(c2549.44,1679.56) 2568.93,1660.07 cw(c2549.44,1679.56) 2549.44,1652 ; 2697.06,2065 ccw(c2697.06,2126.94) 2740.86,2083.14 cw(c2697.06,2126.94) 2697.06,2065 ; 2716.37,2065 cw(c2716.37,2030.37) 2740.86,2054.86 ccw(c2716.37,2030.37) 2716.37,2065 ; 2721.2,2065 ccw(c2721.2,2102.8) 2747.93,2076.07 cw(c2721.2,2102.8) 2721.2,2065
  Bottom Layer w15: v1(1508,1149) 1771.97,1412.97 D3.2@1945,1412.97 1998.97,1412.97 L1.1@2042,1456 ; L1.1@2017.88,1440.63 cw(c2043.41,1433.79) L1.1@2033.57,1458.32 ; 1893.08,1412.97 cw(c1893.08,1365.97) 1926.31,1399.2 ccw(c1893.08,1365.97) 1893.08,1412.97 ; 1893.08,1412.97 ccw(c1893.08,1459.97) 1926.31,1426.73 cw(c1893.08,1459.97) 1893.08,1412.97 ; 1996.92,1412.97 cw(c1996.92,1459.97) 1963.69,1426.73 ccw(c1996.92,1459.97) 1996.92,1412.97 ; 1996.92,1412.97 ccw(c1996.92,1365.97) 1963.69,1399.2 cw(c1996.92,1365.97) 1996.92,1412.97 ; 2007.86,1421.86 ccw(c1973.72,1456) 2022,1456 cw(c1973.72,1456) 2007.86,1421.86
  Bottom Layer w20: v1(1508,1149) 2474,1149 2577,1252 ; C3.1@2577,1652 2577,1252 ; R21.2@2759,2065 2835,1989 2835,1510 2577,1252 ; 2780.61,2043.39 cw(c2806.21,2069) 2770,2069 ccw(c2806.21,2069) 2780.61,2043.39 ; 2780.61,2043.39 ccw(c2755,2017.79) 2755,2054 cw(c2755,2017.79) 2780.61,2043.39 ; C3.1@2565.39,1642.39 cw(c2537.37,1614.37) 2577,1614.37 ccw(c2537.37,1614.37) C3.1@2565.39,1642.39 ; 2577,1619.2 cw(c2609.8,1619.2) 2586.61,1642.39 ccw(c2609.8,1619.2) 2577,1619.2 ; 2798.62,1473.62 ccw(c2754.23,1518) 2817,1518 cw(c2754.23,1518) 2798.62,1473.62 ; C8.2@2821.39,1528.61 ccw(c2788.54,1561.46) 2835,1561.46 cw(c2788.54,1561.46) C8.2@2821.39,1528.61 ; 2835,1546.97 ccw(c2860.97,1546.97) 2842.61,1528.61 cw(c2860.97,1546.97) 2835,1546.97
VCC5V: R18.2 U4.1 U4.2 U5.3 U6.6 | length 2898.6
  Top Layer w30: U4.2@723.31,837 969,1082.69 R18.2@969,1385 ; U4.2@738,828 U5.3@1236.45,828 ; U4.2@785.18,832.12 ccw(c751.79,889.96) 816.3,872.67 ; 788.95,882.56 cw(c750.05,892.98) 770.18,858.11 ccw(c700.58,978.66) 835.04,942.63 ; 791.58,892.39 ccw(c833.04,881.28) U4.2@800.72,853.04 ; U4.2@746.74,837 cw(c803.29,837) 763.3,876.99 ccw(c803.29,837) U4.2@746.74,837 ; U4.2@776.74,837 cw(c905.72,837) 814.52,928.2 ccw(c905.72,837) U4.2@776.74,837 ; U4.2@799.6,854.23 ccw(c862.93,917.56) 862.93,828 cw(c862.93,917.56) U4.2@799.6,854.23 ; U4.2@806.74,837 cw(c1008.14,837) 865.73,979.42 ccw(c1008.14,837) U4.2@806.74,837
  Top Layer w50: U4.1@723.31,737 U4.2@723.31,813.31
  Bottom Layer w10: U6.6@280.87,511.55 495.55,511.55 v1(726,742) ; 352.91,511.55 cw(c352.91,542.25) 331.2,520.54 ccw(c352.91,542.25) 352.91,511.55 ; 352.91,511.55 ccw(c352.91,480.85) 331.2,502.56 cw(c352.91,480.85) 352.91,511.55 ; 714.05,730.05 cw(c726,718.1) 726,735 ccw(c726,718.1) 714.05,730.05 ; 714.05,730.05 ccw(c702.1,742) 719,742 cw(c702.1,742) 714.05,730.05
YELLOW: P2.5 Q2.3 | length 377.5
  Top Layer w15: P2.5@1432,2393 1432,2335.98 Q2.3@1473,2294.97 ; 1454.32,2320.04 cw(c1447.95,2296.25) Q2.3@1469.27,2308.57 ; 1432,2339.82 cw(c1485.18,2339.82) 1447.58,2377.42 ccw(c1485.18,2339.82) 1432,2339.82 ; 1432,2339.82 ccw(c1378.82,2339.82) 1416.42,2377.42 cw(c1378.82,2339.82) 1432,2339.82 ; 1438.76,2329.22 ccw(c1473,2363.46) 1473,2315.03 cw(c1473,2363.46) 1438.76,2329.22
pads on no net: J1.3 J1.4 J2.3 J2.4 J3.3 J3.4 U2.1 U2.2 U2.3 U2.4 U2.17 U2.18 U2.19 U2.21 U2.22 U2.25 U2.26 U2.27 U2.28 U2.29 U2.32 U2.33 U2.38 U2.43 U2.45 U2.46 U6.5 U6.8 U6.10 U6.11 U6.12 U6.13 U6.14 U7.1 U8.1

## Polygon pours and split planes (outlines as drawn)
GND_D on Bottom Layer " GND_D" (solid, pour order 8): 2808,2404 2765,2447 2722,2447 -328,2447 -374,2401 -445,2330 -445,2311 -445,97 -413,65 -381,33 -289,33 2784,33 2827,76 2890,139 2890,217 2890,2322 2848,2364
GND_D on Top Layer " GND_D" (solid, pour order 10): 2831,2381 2765,2447 2697,2447 -329,2447 -392,2384 -445,2331 -445,2305 -445,97 -415,67 -381,33 272,33 2783,33 2865,115 2890,140 2890,179 2890,2322 2841,2371

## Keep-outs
Keep-Out Layer:
  lines w10: -445,97 -381,33 145,33 2784,33 2890,139 2890,2322 2847,2365 2765,2447 237,2447 -329,2447 -445,2331 -445,97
